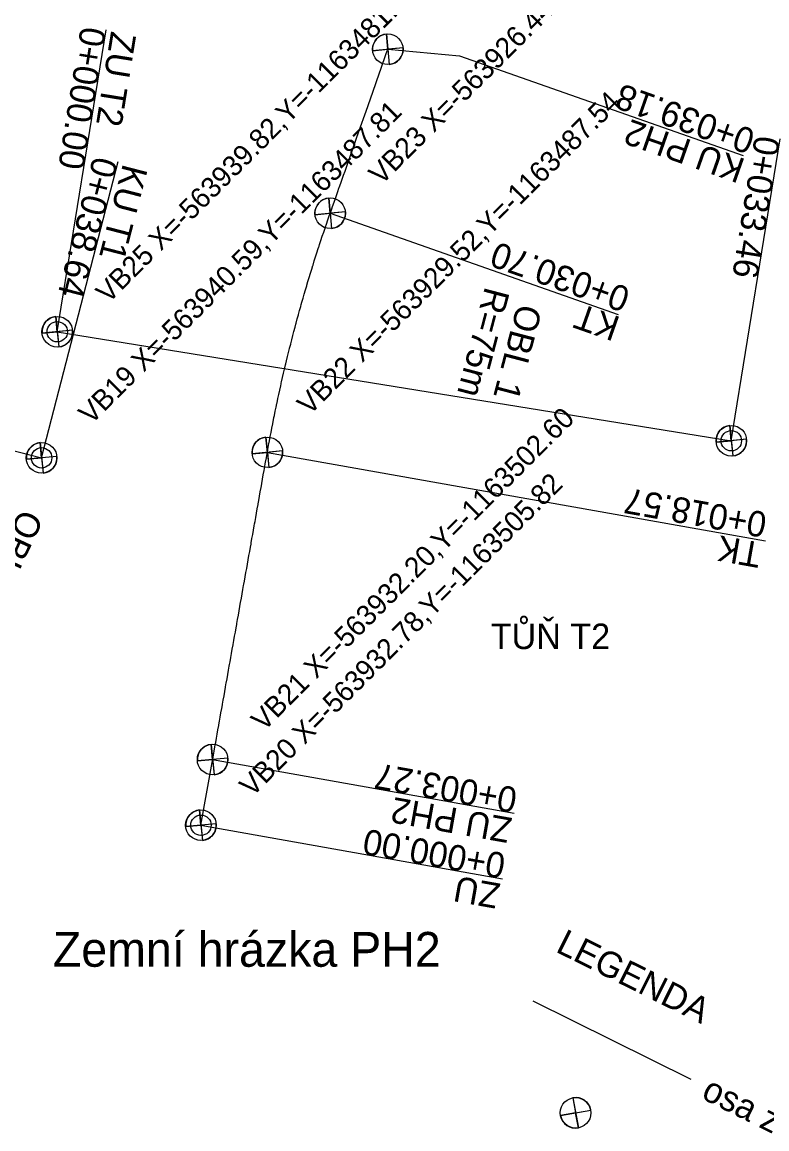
# Model space of a CAD drawing. Extents: x -564052 to -563798, y -1163587 to -1163361.
# Drawn here: x -563941.5 to -563905, y -1163520.7 to -1163466.5 of the extents above; entities that cross this region are included whole.
import ezdxf

# ---------------------------------------------------------------- set-up
doc = ezdxf.new("R2010")
doc.units = 0
for name, color, linetype in [('4', 7, 'Continuous'), ('5', 7, 'Continuous'), ('_popis staničení PH1', 7, 'Continuous'), ('_popis staničení PH2', 7, 'Continuous'), ('_popis staničení T1', 7, 'Continuous'), ('_popis staničení T2', 7, 'Continuous'), ('_rám C35', 7, 'Continuous'), ('Default', 7, 'Continuous')]:
    doc.layers.add(name, color=color, linetype=linetype)

msp = doc.modelspace()

# ---------------------------------------------------------------- linework, layer by layer
msp.add_lwpolyline([(-563932.777, -1163505.823), (-563932.777, -1163505.821), (-563932.167, -1163502.395), (-563932.13, -1163502.186), (-563932.093, -1163501.978), (-563932.076, -1163501.884), (-563932.056, -1163501.77), (-563932.019, -1163501.562), (-563931.982, -1163501.353), (-563931.945, -1163501.145), (-563931.908, -1163500.937), (-563931.901, -1163500.9), (-563931.871, -1163500.728), (-563931.834, -1163500.52), (-563931.796, -1163500.312), (-563931.759, -1163500.103), (-563931.726, -1163499.915), (-563931.722, -1163499.895), (-563931.685, -1163499.687), (-563931.648, -1163499.479), (-563931.611, -1163499.27), (-563931.574, -1163499.062), (-563931.551, -1163498.931), (-563931.537, -1163498.854), (-563931.5, -1163498.645), (-563931.463, -1163498.437), (-563931.426, -1163498.229), (-563931.389, -1163498.02), (-563931.376, -1163497.946), (-563931.352, -1163497.812), (-563931.315, -1163497.604), (-563931.278, -1163497.396), (-563931.241, -1163497.187), (-563931.204, -1163496.979), (-563931.2, -1163496.962), (-563931.166, -1163496.771), (-563931.129, -1163496.562), (-563931.092, -1163496.354), (-563931.055, -1163496.146), (-563931.025, -1163495.977), (-563931.018, -1163495.937), (-563930.981, -1163495.729), (-563930.944, -1163495.521), (-563930.907, -1163495.313), (-563930.87, -1163495.104), (-563930.85, -1163494.993), (-563930.833, -1163494.896), (-563930.796, -1163494.688), (-563930.759, -1163494.479), (-563930.722, -1163494.271), (-563930.685, -1163494.063), (-563930.675, -1163494.008), (-563930.648, -1163493.854), (-563930.611, -1163493.646), (-563930.573, -1163493.438), (-563930.536, -1163493.23), (-563930.5, -1163493.024), (-563930.499, -1163493.021), (-563930.462, -1163492.813), (-563930.425, -1163492.605), (-563930.388, -1163492.396), (-563930.351, -1163492.188), (-563930.325, -1163492.039), (-563930.314, -1163491.98), (-563930.277, -1163491.771), (-563930.24, -1163491.563), (-563930.203, -1163491.355), (-563930.166, -1163491.147), (-563930.149, -1163491.054), (-563930.129, -1163490.938), (-563930.092, -1163490.73), (-563930.055, -1163490.522), (-563930.018, -1163490.313), (-563929.98, -1163490.105), (-563929.974, -1163490.07), (-563929.943, -1163489.897), (-563929.906, -1163489.688), (-563929.869, -1163489.48), (-563929.832, -1163489.272), (-563929.799, -1163489.085), (-563929.795, -1163489.064), (-563929.758, -1163488.855), (-563929.721, -1163488.647), (-563929.684, -1163488.439), (-563929.647, -1163488.23), (-563929.624, -1163488.101), (-563929.61, -1163488.022), (-563929.573, -1163487.814), (-563929.536, -1163487.605), (-563929.524, -1163487.542), (-563929.499, -1163487.397), (-563929.461, -1163487.189), (-563929.447, -1163487.117), (-563929.422, -1163486.981), (-563929.384, -1163486.773), (-563929.344, -1163486.565), (-563929.304, -1163486.357), (-563929.263, -1163486.15), (-563929.26, -1163486.134), (-563929.222, -1163485.942), (-563929.201, -1163485.839), (-563929.18, -1163485.735), (-563929.138, -1163485.528), (-563929.095, -1163485.32), (-563929.06, -1163485.155), (-563929.051, -1163485.113), (-563929.007, -1163484.907), (-563928.962, -1163484.7), (-563928.917, -1163484.493), (-563928.871, -1163484.287), (-563928.846, -1163484.178), (-563928.839, -1163484.145), (-563928.824, -1163484.08), (-563928.777, -1163483.874), (-563928.729, -1163483.668), (-563928.681, -1163483.462), (-563928.632, -1163483.256), (-563928.62, -1163483.204), (-563928.583, -1163483.05), (-563928.533, -1163482.845), (-563928.482, -1163482.639), (-563928.437, -1163482.459), (-563928.431, -1163482.434), (-563928.38, -1163482.233), (-563928.379, -1163482.229), (-563928.327, -1163482.024), (-563928.274, -1163481.819), (-563928.22, -1163481.614), (-563928.166, -1163481.41), (-563928.128, -1163481.265), (-563928.112, -1163481.205), (-563928.056, -1163481.001), (-563928.001, -1163480.797), (-563927.997, -1163480.783), (-563927.944, -1163480.593), (-563927.887, -1163480.389), (-563927.862, -1163480.301), (-563927.83, -1163480.186), (-563927.772, -1163479.982), (-563927.713, -1163479.779), (-563927.654, -1163479.576), (-563927.594, -1163479.373), (-563927.584, -1163479.34), (-563927.534, -1163479.17), (-563927.518, -1163479.118), (-563927.473, -1163478.968), (-563927.411, -1163478.765), (-563927.349, -1163478.563), (-563927.293, -1163478.384), (-563927.286, -1163478.361), (-563927.223, -1163478.159), (-563927.159, -1163477.957), (-563927.095, -1163477.756), (-563927.03, -1163477.554), (-563927, -1163477.464), (-563926.99, -1163477.431), (-563926.964, -1163477.353), (-563926.898, -1163477.152), (-563926.832, -1163476.951), (-563926.764, -1163476.751), (-563926.697, -1163476.55), (-563926.673, -1163476.482), (-563926.628, -1163476.35), (-563926.559, -1163476.15), (-563926.49, -1163475.95), (-563926.445, -1163475.822), (-563926.42, -1163475.751), (-563926.35, -1163475.551), (-563926.345, -1163475.538), (-563926.28, -1163475.351), (-563926.209, -1163475.152), (-563926.139, -1163474.952), (-563926.069, -1163474.753), (-563926.014, -1163474.594), (-563925.999, -1163474.553), (-563925.929, -1163474.353), (-563925.859, -1163474.154), (-563925.789, -1163473.954), (-563925.719, -1163473.755), (-563925.718, -1163473.753), (-563925.682, -1163473.651), (-563925.619, -1163473.47), (-563925.351, -1163472.707), (-563925.019, -1163471.764), (-563924.688, -1163470.82), (-563924.356, -1163469.877), (-563924.025, -1163468.933), (-563923.962, -1163468.753), (-563923.694, -1163467.99), (-563923.633, -1163467.817)])
at = {"layer": '5'}
for p, q in [((-563977.993, -1163478.142), (-563940.586, -1163487.812)), ((-563939.818, -1163481.63), (-563906.789, -1163486.973))]:
    msp.add_line(p, q, dxfattribs=at)
at = {"layer": '_popis staničení PH2'}
for points in [[(-563923.621, -1163467.782), (-563920.11, -1163468.107), (-563906.203, -1163472.993)], [(-563926.445, -1163475.822), (-563912.33, -1163480.781)], [(-563929.524, -1163487.542), (-563905.117, -1163491.884)], [(-563932.204, -1163502.605), (-563917.436, -1163505.232)], [(-563932.777, -1163505.823), (-563918.009, -1163508.45)]]:
    msp.add_lwpolyline(points, dxfattribs=at)
msp.add_circle((-563932.777, -1163505.823), 0.5, dxfattribs=at)
at = {"layer": '_popis staničení T1'}
msp.add_lwpolyline([(-563940.586, -1163487.812), (-563936.832, -1163473.29)], dxfattribs=at)
msp.add_circle((-563940.586, -1163487.812), 0.5, dxfattribs=at)
at = {"layer": '_popis staničení T2'}
for points in [[(-563939.818, -1163481.63), (-563937.423, -1163466.822)], [(-563906.789, -1163486.973), (-563904.394, -1163472.165)]]:
    msp.add_lwpolyline(points, dxfattribs=at)
for centre in [(-563939.818, -1163481.63), (-563906.789, -1163486.973)]:
    msp.add_circle(centre, 0.5, dxfattribs=at)
at = {"layer": '_rám C35'}
for p, q in [((-563923.69, -1163467.035), (-563923.551, -1163468.529)), ((-563923.621, -1163467.782), (-563923.69, -1163467.035)), ((-563923.621, -1163467.782), (-563923.69, -1163467.035)), ((-563924.368, -1163467.851), (-563923.621, -1163467.782)), ((-563924.368, -1163467.851), (-563923.621, -1163467.782)), ((-563922.874, -1163467.712), (-563924.367, -1163467.851)), ((-563922.873, -1163467.712), (-563923.621, -1163467.782)), ((-563923.621, -1163467.782), (-563923.551, -1163468.529)), ((-563926.445, -1163475.822), (-563926.515, -1163475.075)), ((-563926.445, -1163475.822), (-563926.515, -1163475.075)), ((-563926.514, -1163475.076), (-563926.376, -1163476.569)), ((-563925.698, -1163475.753), (-563927.192, -1163475.892)), ((-563927.192, -1163475.892), (-563926.445, -1163475.822)), ((-563927.192, -1163475.892), (-563926.445, -1163475.822)), ((-563925.698, -1163475.753), (-563926.445, -1163475.822)), ((-563926.445, -1163475.822), (-563926.375, -1163476.569)), ((-563939.818, -1163481.63), (-563939.887, -1163480.882)), ((-563939.887, -1163480.883), (-563939.748, -1163482.376)), ((-563939.818, -1163481.63), (-563939.887, -1163480.883)), ((-563939.071, -1163481.56), (-563940.565, -1163481.699)), ((-563940.565, -1163481.699), (-563939.818, -1163481.63)), ((-563940.565, -1163481.699), (-563939.818, -1163481.63)), ((-563939.071, -1163481.56), (-563939.818, -1163481.63)), ((-563939.818, -1163481.63), (-563939.748, -1163482.377)), ((-563906.789, -1163486.973), (-563906.859, -1163486.225)), ((-563906.789, -1163486.973), (-563906.859, -1163486.225)), ((-563906.859, -1163486.226), (-563906.72, -1163487.719)), ((-563929.594, -1163486.795), (-563929.455, -1163488.288)), ((-563929.524, -1163487.542), (-563929.594, -1163486.795)), ((-563929.524, -1163487.542), (-563929.594, -1163486.795)), ((-563940.656, -1163487.065), (-563940.517, -1163488.559)), ((-563940.586, -1163487.812), (-563940.656, -1163487.065)), ((-563940.586, -1163487.812), (-563940.656, -1163487.065)), ((-563906.042, -1163486.903), (-563907.536, -1163487.042)), ((-563907.536, -1163487.042), (-563906.789, -1163486.973)), ((-563907.536, -1163487.042), (-563906.789, -1163486.973)), ((-563906.042, -1163486.903), (-563906.789, -1163486.973)), ((-563906.789, -1163486.973), (-563906.72, -1163487.72)), ((-563939.839, -1163487.743), (-563941.333, -1163487.882)), ((-563941.333, -1163487.882), (-563940.586, -1163487.812)), ((-563941.333, -1163487.882), (-563940.586, -1163487.812)), ((-563939.839, -1163487.743), (-563940.586, -1163487.812)), ((-563940.586, -1163487.812), (-563940.517, -1163488.559)), ((-563930.272, -1163487.611), (-563929.524, -1163487.542)), ((-563930.272, -1163487.611), (-563929.524, -1163487.542)), ((-563928.778, -1163487.472), (-563930.271, -1163487.611)), ((-563928.777, -1163487.472), (-563929.524, -1163487.542)), ((-563929.524, -1163487.542), (-563929.455, -1163488.289)), ((-563932.274, -1163501.858), (-563932.135, -1163503.351)), ((-563932.204, -1163502.605), (-563932.274, -1163501.858)), ((-563932.204, -1163502.605), (-563932.274, -1163501.858)), ((-563931.458, -1163502.535), (-563932.951, -1163502.674)), ((-563931.457, -1163502.535), (-563932.204, -1163502.605)), ((-563932.952, -1163502.674), (-563932.204, -1163502.605)), ((-563932.952, -1163502.674), (-563932.204, -1163502.605)), ((-563932.204, -1163502.605), (-563932.135, -1163503.352)), ((-563932.777, -1163505.823), (-563932.847, -1163505.075)), ((-563932.777, -1163505.822), (-563932.846, -1163505.075)), ((-563932.846, -1163505.076), (-563932.707, -1163506.569)), ((-563932.03, -1163505.753), (-563933.524, -1163505.892)), ((-563933.524, -1163505.892), (-563932.777, -1163505.822)), ((-563933.524, -1163505.892), (-563932.777, -1163505.823)), ((-563932.03, -1163505.753), (-563932.777, -1163505.823)), ((-563932.777, -1163505.823), (-563932.707, -1163506.57)), ((-563916.518, -1163514.429), (-563908.771, -1163518.281)), ((-563914.551, -1163519.184), (-563914.285, -1163520.66)), ((-563914.551, -1163519.184), (-563914.418, -1163519.922)), ((-563914.418, -1163519.922), (-563915.157, -1163520.055)), ((-563914.418, -1163519.922), (-563915.157, -1163520.055)), ((-563915.156, -1163520.055), (-563913.68, -1163519.79)), ((-563914.418, -1163519.922), (-563913.68, -1163519.79)), ((-563914.285, -1163520.661), (-563914.418, -1163519.922)), ((-563914.285, -1163520.661), (-563914.418, -1163519.922))]:
    msp.add_line(p, q, dxfattribs=at)
for centre in [(-563923.621, -1163467.782), (-563926.445, -1163475.822), (-563939.818, -1163481.63), (-563906.789, -1163486.973), (-563929.524, -1163487.542), (-563940.586, -1163487.812), (-563932.204, -1163502.605), (-563932.777, -1163505.823), (-563914.418, -1163519.922)]:
    msp.add_circle(centre, 0.75, dxfattribs=at)
for centre, start, end in [((-563923.621, -1163467.782), 95.3168, 185.3168), ((-563923.621, -1163467.782), 95.3168, 185.3168), ((-563923.621, -1163467.782), 275.3168, 5.3168), ((-563926.445, -1163475.822), 95.3168, 185.3168), ((-563926.445, -1163475.822), 95.3168, 185.3168), ((-563926.445, -1163475.822), 275.3168, 5.3168), ((-563939.818, -1163481.63), 95.3168, 185.3168), ((-563939.818, -1163481.63), 95.3168, 185.3168), ((-563939.818, -1163481.63), 275.3168, 5.3168), ((-563906.789, -1163486.973), 95.3168, 185.3168), ((-563906.789, -1163486.973), 95.3168, 185.3168), ((-563929.524, -1163487.542), 95.3168, 185.3168), ((-563929.524, -1163487.542), 95.3168, 185.3168), ((-563940.586, -1163487.812), 95.3168, 185.3168), ((-563940.586, -1163487.812), 95.3168, 185.3168), ((-563906.789, -1163486.973), 275.3168, 5.3168), ((-563940.586, -1163487.812), 275.3168, 5.3168), ((-563929.524, -1163487.542), 275.3168, 5.3168), ((-563932.204, -1163502.605), 95.3168, 185.3168), ((-563932.204, -1163502.605), 95.3168, 185.3168), ((-563932.204, -1163502.605), 275.3168, 5.3168), ((-563932.777, -1163505.823), 95.3168, 185.3168), ((-563932.777, -1163505.822), 95.3168, 185.3168), ((-563932.777, -1163505.823), 275.3168, 5.3168), ((-563914.418, -1163519.922), 10.1902, 100.1902), ((-563914.418, -1163519.922), 190.1902, 280.1902), ((-563914.418, -1163519.922), 190.1902, 280.1902)]:
    msp.add_arc(centre, 0.75, start, end, dxfattribs=at)

# ---------------------------------------------------------------- texts
at = {"layer": '4'}
for s, height, p in [('TŮŇ T2', 1.25, (-563918.578, -1163497.186)), ('Zemní hrázka PH2', 1.70472, (-563940.033, -1163512.761))]:
    msp.add_text(s, height=height, rotation=360, dxfattribs=at).set_placement(p)
at = {"layer": '_popis staničení PH1'}
msp.add_text('OBL 1', height=1.25, rotation=244.8543, dxfattribs=at).set_placement((-563941.595, -1163490.259))
at = {"layer": '_popis staničení PH2'}
for s, rotation, p in [('0+039.18', 160.6443, (-563905.543, -1163471.771)), ('KU PH2 ', 160.6443, (-563906.04, -1163473.186)), ('0+030.70', 160.6443, (-563911.669, -1163479.521)), ('R=75m ', 255.2778, (-563918.848, -1163479.378)), ('OBL 1', 255.2778, (-563917.257, -1163480.21)), ('KT ', 160.6443, (-563912.166, -1163480.936)), ('0+018.57', 169.9113, (-563904.985, -1163490.505)), ('TK ', 169.9113, (-563905.248, -1163491.982)), ('0+003.27', 169.9113, (-563917.217, -1163504.002)), ('ZU PH2 ', 169.9113, (-563917.48, -1163505.478)), ('0+000.00', 169.9113, (-563917.79, -1163507.219)), ('ZU ', 169.9113, (-563918.053, -1163508.696))]:
    msp.add_text(s, height=1.25, rotation=rotation, dxfattribs=at).set_placement(p)
at = {"layer": '_popis staničení T1'}
for s, p in [('0+038.64', (-563938.042, -1163472.977)), ('KU T1 ', (-563936.59, -1163473.352))]:
    msp.add_text(s, height=1.25, rotation=255.5058, dxfattribs=at).set_placement(p)
at = {"layer": '_popis staničení T2'}
for s, p in [('0+000.00', (-563938.657, -1163466.623)), ('ZU T2 ', (-563937.176, -1163466.862)), ('0+033.46', (-563905.628, -1163471.965))]:
    msp.add_text(s, height=1.25, rotation=260.811, dxfattribs=at).set_placement(p)
at = {"layer": '_rám C35'}
for s, height, p in [('LEGENDA', 1.257, (-563915.447, -1163512.003)), ('osa zemní hrázky, tůně, odpadního příkopu, odpadního průlehu', 1.25, (-563908.317, -1163519.191))]:
    msp.add_text(s, height=height, rotation=333.563, dxfattribs=at).set_placement(p)
at = {"layer": 'Default'}
for s, p in [('VB23 X=-563926.44,Y=-1163475.82', (-563923.945, -1163474.474)), ('VB25 X=-563939.82,Y=-1163481.63', (-563937.318, -1163480.281)), ('VB22 X=-563929.52,Y=-1163487.54', (-563927.455, -1163485.763)), ('VB19 X=-563940.59,Y=-1163487.81', (-563938.16, -1163486.219)), ('VB21 X=-563932.20,Y=-1163502.60', (-563929.705, -1163501.256)), ('VB20 X=-563932.78,Y=-1163505.82', (-563930.277, -1163504.474))]:
    msp.add_text(s, height=1, rotation=45, dxfattribs=at).set_placement(p)

doc.saveas('drawing.dxf')
